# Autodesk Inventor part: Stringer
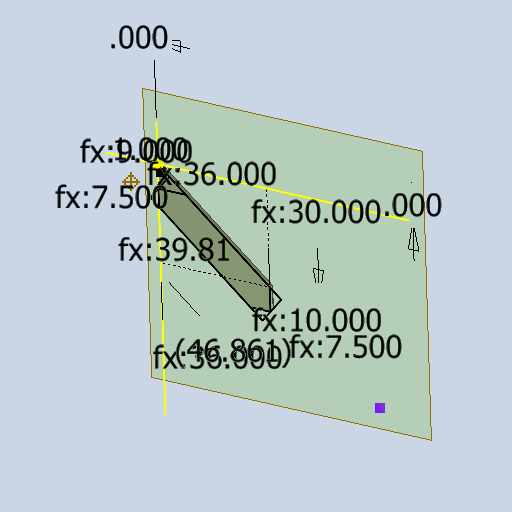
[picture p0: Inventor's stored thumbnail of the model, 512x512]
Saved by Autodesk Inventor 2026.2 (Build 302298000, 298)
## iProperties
Created: 2022-06
Part Number: Stringer
Material: Steel, Galvanized
Document SubType Name: Modeling
Designer: reaumed
Density: 7.85 g/cm^3
Appearance: Galvanized
Mass: 28099.6 g
Surface Area: 11501.7 cm^2
Volume: 3579.57 cm^3
Author: reaumed
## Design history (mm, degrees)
node "Half the Width Workplane"
sketch "Stringer Profile Sketch"
  geometry: L1 (0, 0)-(-914.4, 0); L2 (-914.4, 0)-(-914.4, -762); L3 (-914.4, -762)-(0, -762); L4 (0, -762)-(0, 0); L5 (-845.482, -1035.202)-(68.918, -273.202); L6 (68.918, -273.202)-(-93.689, -78.074); L7 (-93.689, -78.074)-(-1008.089, -840.074); L8 (-1008.089, -840.074)-(-845.482, -1035.202); L9 (0, -190.5)-(-228.6, -190.5); L10 (0, -190.5)-(0, -330.634); L11 (-746.239, -952.5)-(-914.4, -952.5); L12 (-914.4, -952.5)-(-914.4, -762); L13 (0, -1935.112)-(0, 322.519) reference; L14 (-2103.33, 0)-(428.779, 0) reference; L15 (0, -190.5)-(0, -54.23); L16 (-93.689, -78.074)-(-41.661, -34.717); A1 r 25.4 centre (-25.4, -54.23) between (0, -54.23) and (-41.661, -34.717); 8 further points
  constraints: 28 end point, 9 point on line, 4 parallel, 3 horizontal, 2 collinear, 2 perpendicular, 2 point on circle, 2 tangent, 2 vertical, 1 centre point
  dimensions: "d152" = 762 distance of L1.end L2.end (derived); "d153" = 914.4 distance of L2.end L3.end (derived); "d155" = 254 distance of L7.end L5.start (derived); "d156" = 1190.28205 distance of L6.end L7.end (derived); "d157" = 39.8056 deg angle of L3 L5 (derived); "d158" = 228.6 distance of L9.start L9.end (derived); "d159" = 190.5 distance of L11.end L12.end (derived); "d160" = 190.5 distance between parallel lines of L1 L9 (derived); "d161" = 914.4 distance between parallel lines of L12 L10 (derived); "d162" = 0 distance between parallel lines of L4 L13; "d163" = 0 distance between parallel lines of L1 L14; "d190" = 25.4 radius of A1 (derived)
extrude "Stringer Extrusion" new body sketch "Stringer Profile Sketch" distance "d164" = 38.1 (derived); taper "d165" = 0 deg
shell "Shell1" dims "d189" = 6.35 (derived)
body "Solid2"
other parameters: "StringerSpacing" = 342.9 (derived), "StringerWallThickness" = 6.35 [user parameter]
